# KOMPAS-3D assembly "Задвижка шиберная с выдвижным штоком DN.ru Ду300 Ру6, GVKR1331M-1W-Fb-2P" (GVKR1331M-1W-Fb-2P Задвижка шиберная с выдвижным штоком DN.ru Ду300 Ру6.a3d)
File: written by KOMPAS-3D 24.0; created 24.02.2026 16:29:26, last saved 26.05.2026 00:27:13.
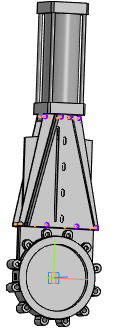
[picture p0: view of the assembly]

Document properties: Автор: R2D2; Полное имя файла: E:\Работа\Зайцев\GVKR1331M-1W-Fb-2P Задвижка шиберная с выдвижным штоком DN.ru Ду50-300 Ру16-10-6 с пневмоприводом\исходные материалы\DN300\GVKR1331M-1W-Fb-2P Задвижка шиберная с выдвижным штоком DN.ru Ду300 Ру6.a3d

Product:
- Component [detail]: Затвор дисковый DN.ru Ду Ру  | qty 1  | pos. 1  | Масса: 18.2; Раздел спецификации: Прочие изделия; Примечание: D050-23732; Автор: R2D2; source file: Задвижка шиберная РЕЗЬБОВОЙ DN.ru Ду Ру.m3d
- Component [detail]: Пневмоцилиндр  | qty 1  | pos. 2  | Масса: 96.248058; Автор: R2D2; source file: Пневмоцилиндр.m3d
- Component [standard]: Hexagon head screw ISO 4017 - М10 x 25  | qty 8  | pos. 5  | Масса: 0.026096; Раздел спецификации: Стандартные изделия; Рассекать на разрезах: no
- Component [detail]: лист  | qty 2  | pos. 3  | Масса: 5.441535; Раздел спецификации: Прочие изделия; Примечание: D040-08800; Автор: R2D2; source file: лист.m3d
- Component [detail]: шибер  | qty 1  | pos. 4  | Масса: 10.072199; Раздел спецификации: Прочие изделия; Примечание: D040-08800; Автор: R2D2; source file: шибер.m3d
- Component [standard]: Hexagon head screw ISO 4017 - М8 x 16  | qty 8  | Масса: 0.012085; Раздел спецификации: Стандартные изделия; Рассекать на разрезах: no
- Part/product: Задвижка шиберная с выдвижным штоком DN.ru Ду300 Ру6  | designation GVKR1331M-1W-Fb-2P
    Масса: 70
    Раздел спецификации: Прочие изделия
    Примечание: D040-08799

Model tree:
1. Точка:1  (with: Ребро.Отверстие в листовом теле:2)
     X = -72.8566; Y = 232.5; Z = 74
2. Точка:2  (with: Ребро.Отверстие в листовом теле:3)
     X = 72.8566; Y = 232.5; Z = 74
3. Точка:3  (with: Ребро.Отверстие в листовом теле:4)
     X = 182.724; Y = 232.5; Z = 36.5
4. Точка:4  (with: Ребро.Отверстие в листовом теле:5)
     X = -82.3702; Y = 718.5; Z = 36.5
5. Точка:5  (with: Ребро.Отверстие в листовом теле:6)
     X = -20.2251; Y = 718.5; Z = 74
6. Точка:6  (with: Ребро.Отверстие в листовом теле:7)
     X = 20.2251; Y = 718.5; Z = 74
7. Точка:7  (with: Ребро.Отверстие в листовом теле:8)
     X = 82.3702; Y = 718.5; Z = 36.5
8. Массив по точкам:1
9. Экземпляр ( 6 )
10. Экземпляр ( 4 )
11. Экземпляр ( 1 )
12. Экземпляр ( 7 )
13. Экземпляр ( 3 )
14. Экземпляр ( 5 )
15. Экземпляр ( 2 )
16. Контекстная связь:1  (with: Эскиз:7, Грань.Элемент выдавливания:6, Ребро.Элемент выдавливания:6, Ребро.Элемент выдавливания:12, Контекстная связь (лист (1)):1)
17. Контекстная связь:2  (with: Эскиз:6, Грань.Элемент выдавливания:15, Ребро.Элемент выдавливания:15, Контекстная связь (лист (1)):2)
18. Контекстная связь:3  (with: Эскиз:5, Грань.Элемент выдавливания:1, Вершина.Элемент выдавливания:15, Контекстная связь (шибер):3, Грань.Элемент выдавливания:8, Грань.Линейчатая обечайка:1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)
     Ориентация = 2; Ориентация = 2; Ориентация = 2; Ориентация = 2; Ориентация = 2; Ориентация = 2; Ориентация = 2; Ориентация = 2; Ориентация = 2

Expressions: D050-23732; D040-08800
Referenced files in E:\Работа\Зайцев\GVKR1331M-1W-Fb-2P Задвижка шиберная с выдвижным штоком DN.ru Ду50-300 Ру16-10-6 с пневмоприводом\исходные материалы\DN300\: Задвижка шиберная РЕЗЬБОВОЙ DN.ru Ду Ру.m3d, Пневмоцилиндр.m3d, лист.m3d, шибер.m3d
Referenced files in C:\Program Files\ASCON\KOMPAS-3D v24\Libs\PolynomLib\DATA\vault\Methods\Kompas\3D\: PLib_Bolt_1_ISO_1100.m3d
Referenced files in E:\Работа\Зайцев\GVKR1331E-1W-Fb-2P Задвижка шиберная DN.ru Ду50-300 Ру16-10-6\исходные материалы\DN80\: лист.m3d
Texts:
  Hexagon head screw
  BOSimple***PART:f114febc-ab7b-6638-bb5e-15f0e2e47160***SHORTLOC:A259_7B16EF33AB1642D2[16;1,5;25;10;-;Undefined]
  BOSimple***PART:17775d1c-e7de-f283-40f0-d40789f7f59e***SHORTLOC:A259_7B16EF33AB1642D2[13;1,25;16;8;-;Undefined]
  Программные изделия  и базы данных
  GVKR1331M-1W-Fb-2P
  Hexagon head screw ISO 4017 - М10 x 25 (1)
  hole1
  hole2
  лист (1)
  лист (2)
  Hexagon head screw ISO 4017 - М8 x 16 (1)
  Hexagon head screw ISO 4017 - М8 x 16 (2)
  Hexagon head screw ISO 4017 - М8 x 16 (3)
  Hexagon head screw ISO 4017 - М8 x 16 (4)
  Hexagon head screw ISO 4017 - М8 x 16 (5)
  Hexagon head screw ISO 4017 - М8 x 16 (6)
  Hexagon head screw ISO 4017 - М8 x 16 (7)
  Hexagon head screw ISO 4017 - М8 x 16 (8)
  Ось Y.Начало координат
  Плоскость ZY.Начало координат
  Плоскость ZX.Начало координат
  Плоскость XY.Начало координат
